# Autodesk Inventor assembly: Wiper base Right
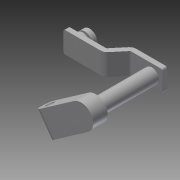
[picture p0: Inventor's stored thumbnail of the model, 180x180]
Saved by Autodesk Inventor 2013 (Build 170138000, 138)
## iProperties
Created: 2006-03
Part Number: Wiper base Right
Document SubType Name: Assembly
Designer: Autodesk, Inc.
Mass: 335.369 g
Surface Area: 167.286 cm^2
Volume: 43.2734 cm^3
Density: 7.75 g/cm^3
Author: Autodesk, Inc.
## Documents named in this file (5)
- C:\Users\boganb\Documents\B2 Design\Goodyear\2013 Tutorial Files\Dynamic Simulation 4\Components\Wiper base Right.iam
- C:\Users\boganb\Documents\B2 Design\Goodyear\2013 Tutorial Files\Dynamic Simulation 4\Components\Axis_Right.ipt
- C:\Users\boganb\Documents\B2 Design\Goodyear\2013 Tutorial Files\Dynamic Simulation 4\Components\Support_Wiper.ipt
- C:\Users\boganb\Documents\B2 Design\Goodyear\2013 Tutorial Files\Dynamic Simulation 4\Components\Crank_right.ipt
- C:\Users\boganb\Documents\B2 Design\Goodyear\2013 Tutorial Files\Dynamic Simulation 4\Components\Pawn.ipt
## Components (4 placed, 4 different names)
1. Axis_Right:1 — Mate:18, Flush:4, Angle:9, Mate:32, Mate:33, Mate:34
2. Support_Wiper:1 — Mate:18, Flush:4, Angle:9
3. Crank_right:1 — Mate:29, Mate:30, Mate:31, Mate:32, Mate:33, Mate:34, Mate:35, Mate:36, Angle:10, Angle:11
4. Pawn:1 — Mate:35, Mate:36, Mate:39, Flush:5
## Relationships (15: Mate 10, Angle 3, Flush 2)
- Mate:18: Axis_Right:1 ↔ Support_Wiper:1
- Flush:4: Axis_Right:1 ↔ Support_Wiper:1
- Angle:9: Axis_Right:1 ↔ Support_Wiper:1
- Mate:29: Crank_right:1
- Mate:30: Crank_right:1
- Mate:31: Crank_right:1
- Mate:32: Axis_Right:1 ↔ Crank_right:1
- Mate:33: Axis_Right:1 ↔ Crank_right:1
- Mate:34: Axis_Right:1 ↔ Crank_right:1
- Mate:35: Crank_right:1 ↔ Pawn:1
- Mate:36: Crank_right:1 ↔ Pawn:1
- Mate:39: Pawn:1
- Angle:10: Crank_right:1
- Flush:5: Pawn:1
- Angle:11: Crank_right:1
